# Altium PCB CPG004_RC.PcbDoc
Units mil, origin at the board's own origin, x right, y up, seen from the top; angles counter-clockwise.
Board outline 5000 x 5000 mil, 4 copper layers (Top Layer, Kelvin, GND_Plane, Bottom Layer); 96 components, 88 nets, 618 pads, 128 vias.
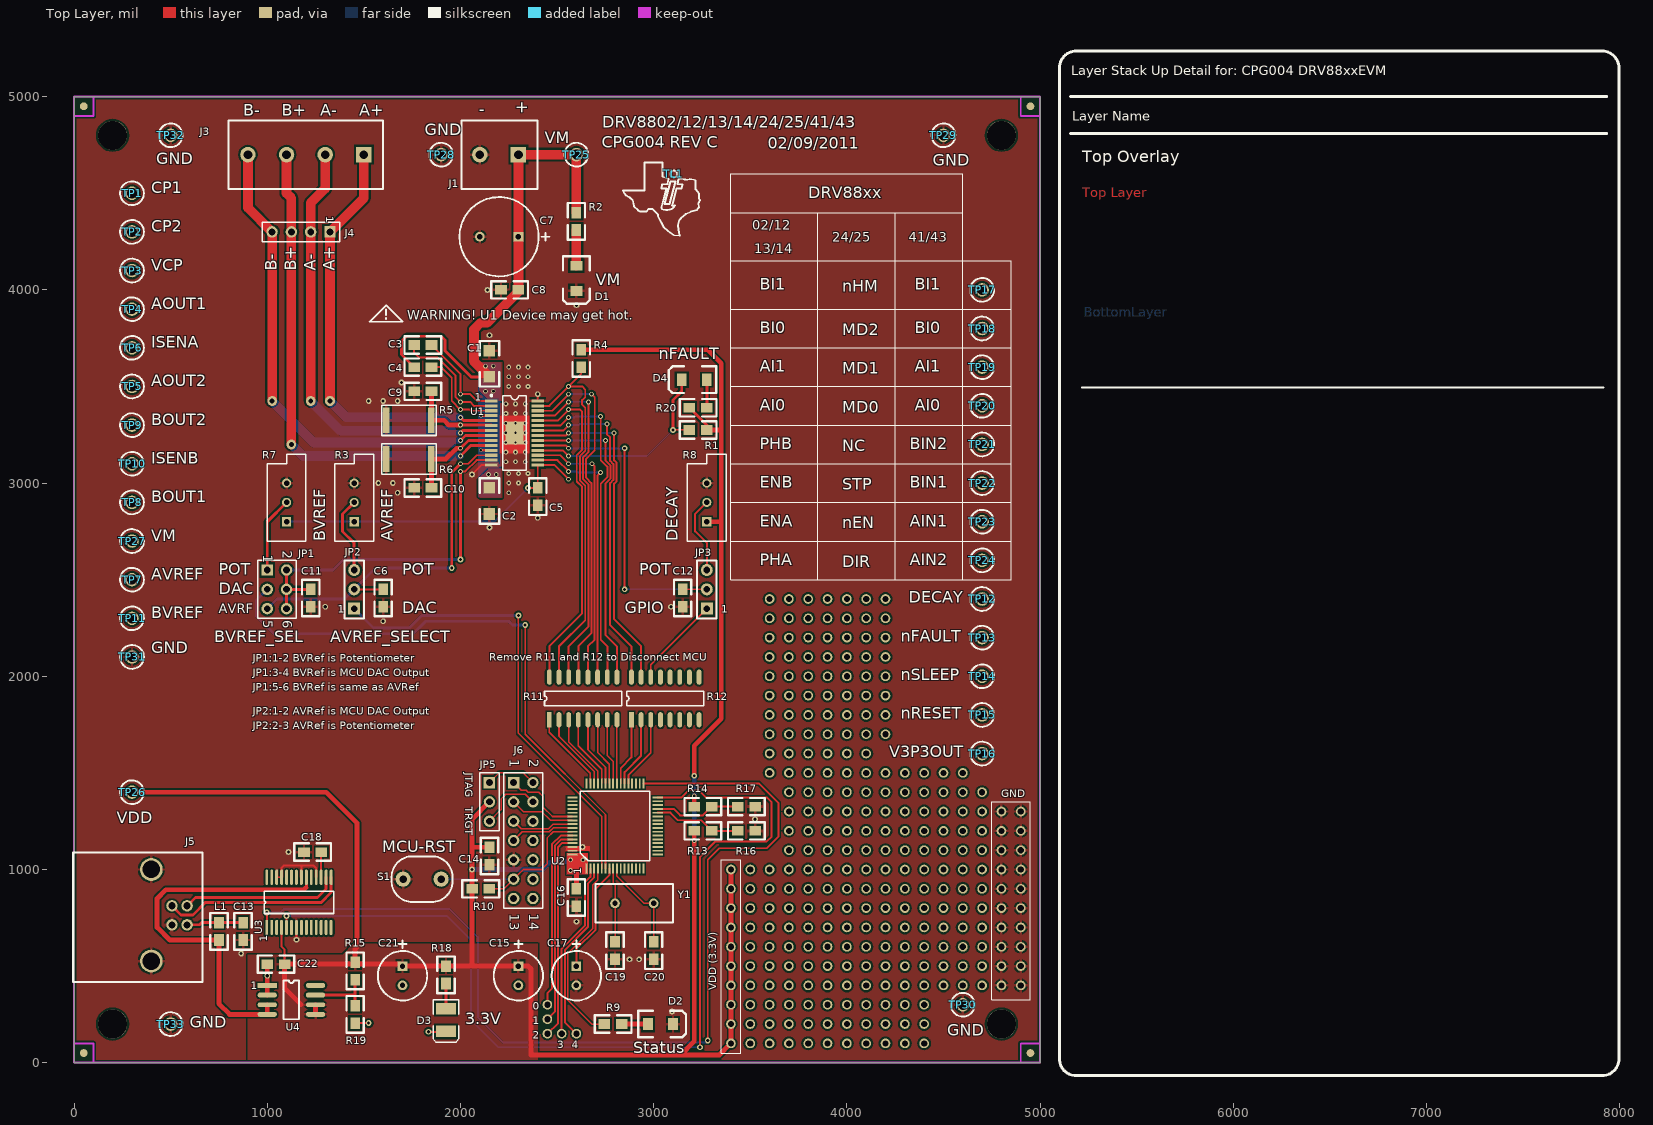
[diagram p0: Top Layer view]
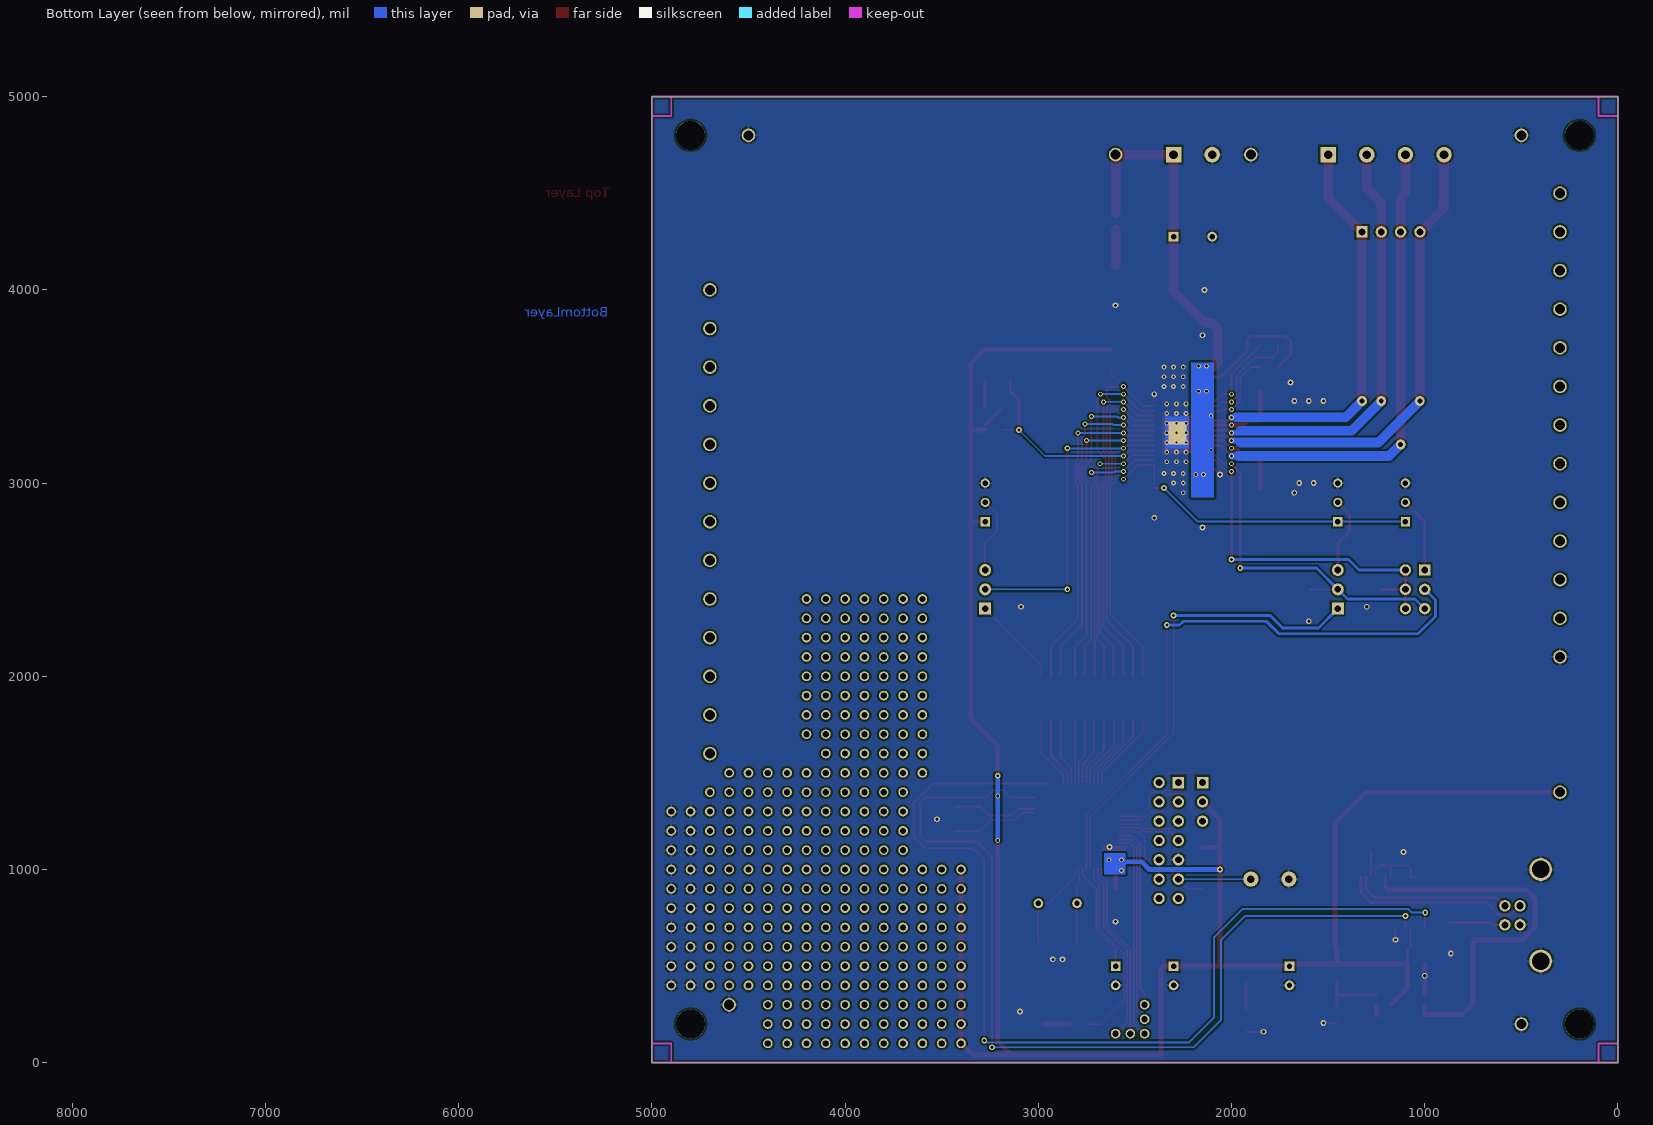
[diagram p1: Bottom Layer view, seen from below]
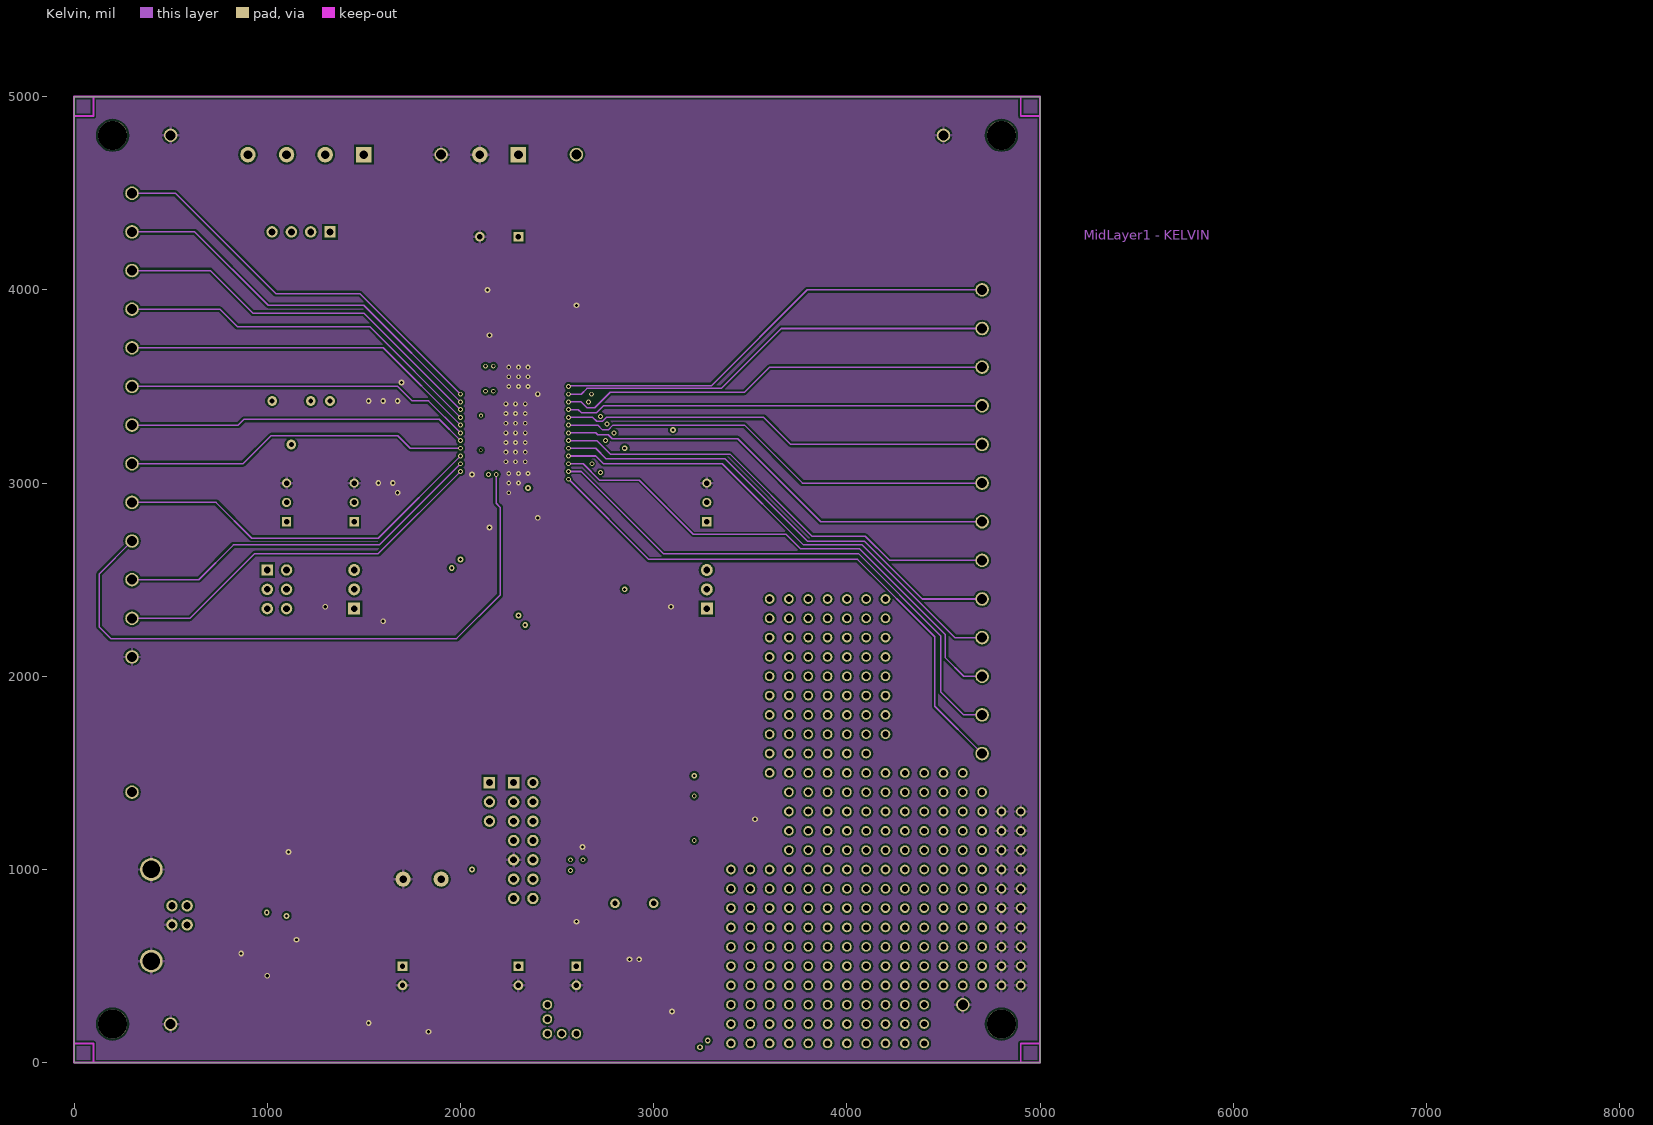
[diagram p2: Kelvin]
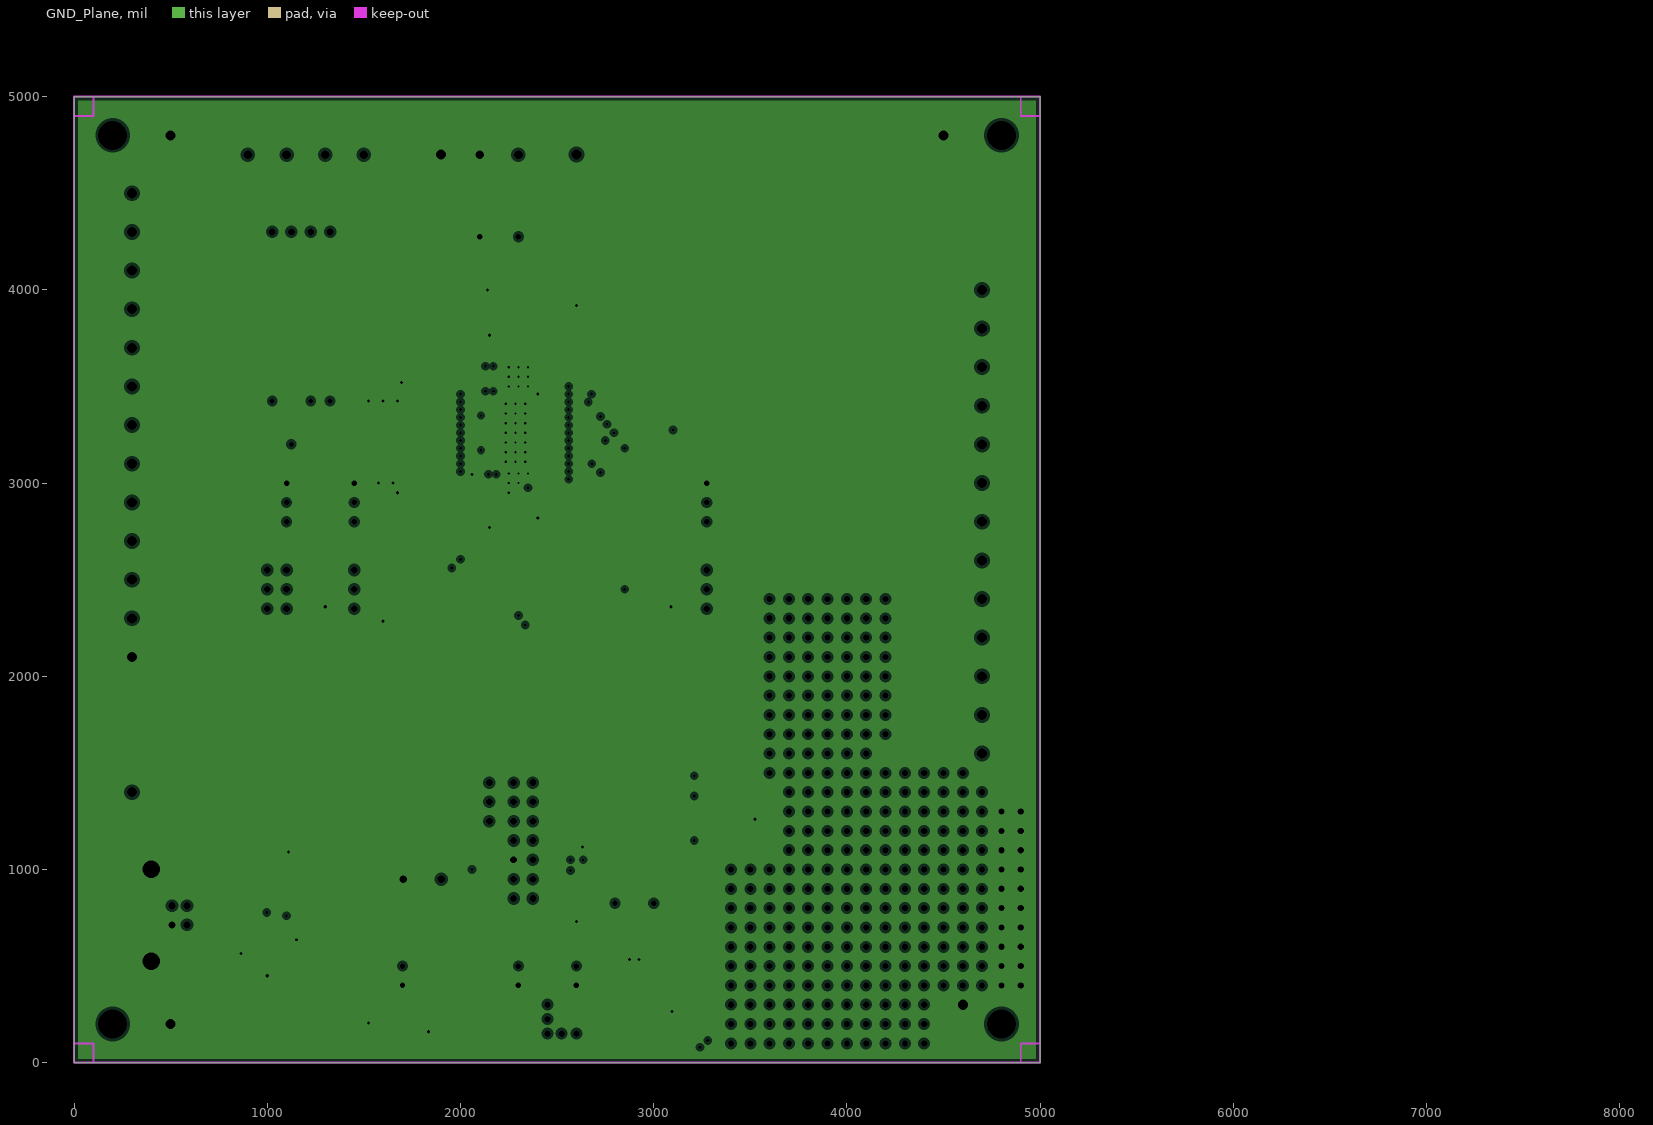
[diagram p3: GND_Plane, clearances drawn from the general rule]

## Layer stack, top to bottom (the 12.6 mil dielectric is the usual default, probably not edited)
Top Layer: signal copper 1.4
Dielectric: core 12.6, FR-4, Dk 4.8
Kelvin: signal copper 1.4
Dielectric: prepreg 12.6, FR-4, Dk 4.8
GND_Plane: plane copper 1.4, net GND
Dielectric: core 12.6, FR-4, Dk 4.8
Bottom Layer: signal copper 1.4

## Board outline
0,0 5000,0 5000,5000 0,5000

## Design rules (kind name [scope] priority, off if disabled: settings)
Clearance Clearance_2 [InNamedPolygon('KLV_GND') Or  InNamedPolygon('TOP_VDD') Or  InNamedPolygon('BOT_GND') Or  InNamedPolygon('TOP_GND')] p1: gap=10
Clearance [All] p2: gap=6
HoleSize [All] p1: absolutevalues=TRUE maxlimit=360 minlimit=1 maxpercent=80.000 minpercent=20.000
PlaneClearance [All] p1: clearance=15
PlaneConnect [All] p1: planeconnectstyle=Relief reliefexpansion=15 reliefentries=4 reliefconductorwidth=20 reliefairgap=8
PolygonConnect GND_VIA [(InNet('GND')) vs IsVia] p1: connectstyle=Direct reliefconductorwidth=10 reliefentries=4 polygonreliefangle="90 Angle"
PolygonConnect PolygonConnect_1 [All vs IsNamedPolygon('TOP_PIN_GND')] p2: connectstyle=Direct reliefconductorwidth=10 reliefentries=4 polygonreliefangle="90 Angle"
PolygonConnect PolygonConnect_2 [All vs IsNamedPolygon('TOP_VM') or isnamedpolygon('TOP_VMB')] p3: connectstyle=Direct reliefconductorwidth=10 reliefentries=4 polygonreliefangle="90 Angle"
PolygonConnect [All] p4: connectstyle=Relief reliefconductorwidth=15 reliefentries=4 polygonreliefangle="90 Angle"
RoutingLayers [All] p1: top layer_v5=TRUE mid layer 1_v5=FALSE bottom layer_v5=TRUE
RoutingVias [All] p1: holewidth=15 width=25 viastyle="Through Hole" minholewidth=10 minwidth=20 maxholewidth=25 maxwidth=70
SilkscreenOverComponentPads [All] p1: minsilkscreentomaskgap=10
SolderMaskExpansion [All] p1: expansion=4
TestPointUsage [All] p1: valid=2 allowmultiple=FALSE
Testpoint [All] p1: side=15 testpointundercomponent=TRUE minsize=40 maxsize=100 preferedsize=60 minholesize=0 maxholesize=40 preferedholesize=32 testpointgrid=1 style=1023 order=0123456789
Width [All] p1: maxlimit=100 minlimit=8 preferedwidth=8 toplayer_prefwidth=10 midlayer1_maxwidth=8 bottomlayer_prefwidth=50 minimp=50.000000 maximp=50.000000 favimp=50.000000
19 further rules are at their usual default settings.

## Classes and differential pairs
component class CPG004_RC_TS: TP1 TP2 TP3 TP4 TP5 TP6 TP7 TP8 TP9 TP10 TP11 TP12 TP13 TP14 TP15 TP16 TP17 TP18 TP19 TP20 TP21 TP22 TP23 TP24 TP25 TP26 TP27 TP28 TP29 TP30 TP31 TP32 TP33
component class CPG004_RC: C1 C2 C3 C4 C5 C6 C7 C8 C9 C10 C11 C12 D1 D4 J1 J3 J4 JP1 JP2 JP3 R1 R2 R3 R4 R5 R6 R7 R8 R20 TL1 U1
polygon class PinPolygons: Bottom-GND VDD
component class CPG004_RC_MSP430: C13 C14 C15 C16 C17 C18 C19 C20 C21 C22 D2 D3 J5 J6 JP5 L1 R9 R10 R11 R12 R13 R14 R15 R16 R17 R18 R19 S1 U2 U3 U4 Y1

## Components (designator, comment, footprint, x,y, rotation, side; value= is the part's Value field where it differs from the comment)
C1 "" 1206 2150,3685 r270 top
C2 "" 1206 2150,2840 r90 top
C3 "0.01uF" 0805 1850,3715 r180 top
C4 "" 0805 1760,3600 r0 top
C5 "" 0805 2400,2885 r90 top
C6 "" 0805 1600,2360 r90 top
C7 "" "RB .2/.4 SS" 2100,4275 r0 top
C8 "" 0805 2210,4000 r0 top
C9 "" 0805 1760,3475 r0 top
C10 "" 0805 1760,2975 r0 top
C11 "" 0805 1225,2360 r90 top
C12 "" 0805 3150,2360 r90 top
C13 "Cap" 0805 875,635 r90 top
C14 "Cap" 0805 2150,1025 r90 top
C15 "Cap Pol1" "RB .1/.250" 2300,400 r270 top
C16 "Cap" 0805 2600,810 r90 top
C17 "Cap Pol1" "RB .1/.250" 2600,400 r270 top
C18 "Cap" 0805 1190,1090 r0 top
C19 "Cap" 0805 2800,535 r90 top
C20 "Cap" 0805 3000,535 r90 top
C21 "Cap Pol1" "RB .1/.250" 1700,400 r270 top
C22 "Cap1" 0805 1000,510 r0 top
D1 "VM" 1206_LED 2600,4125 r270 top
D2 "Status" 1206_LED 2970.08,200 r0 top
D3 "3.3V" 3.5X2.8X1.9 1925,220.94 r270 top
D4 "nFAULT" 1206_LED 3275,3535 r180 top
J1 "VM" PWR_CONN2 2300,4700 r180 top
J3 "Header 4" PWR_CONN4 1500,4700 r180 top
J4 "Header 4" HDR1X4 1325,4300 r180 top
J5 "USB B Conn" USB_CONN 506.69,812.2 r270 top
J6 "JTAG" HDR2X7 2275,1450 r270 top
JP1 "BVREF_SEL" HDR2X3 1000,2550 r270 top
JP2 "AVREF_SELECT" JMP0.3 1450,2350 r90 top
JP3 "DECAY_SEL" JMP0.3 3275,2350 r90 top
JP5 "PWR Select" HDR1X3 2150,1450 r270 top
L1 "" 0805 750,725 r270 top
R1 "" 0805 3275,3275 r180 top
R2 "Res2" 0805 2600,4400 r270 top
R3 "AVREF" VR5 1450,2900 r90 top
R4 "" 0805 2625,3690 r270 top
R5 "" 2512 1850,3325 r180 top
R6 "" 2512 1850,3125 r180 top
R7 "BVREF" VR5 1100,2900 r90 top
R8 "DECAY" VR5 3275,2900 r90 top
R9 "Res2" 0805 2835.08,200 r180 top
R10 "" 0805 2060,900 r0 top
R11 "Res Pack3" RES_NET_8 2460,1775 r90 top
R12 "Res Pack3" RES_NET_8 2885,1775 r90 top
R13 "" 0805 3210,1200 r0 top
R14 "" 0805 3210,1325 r0 top
R15 "Res2" 0805 1455,430 r90 top
R16 "" 0805 3435,1200 r0 top
R17 "" 0805 3435,1325 r0 top
R18 "Res1" 0805 1925,410 r90 top
R19 "Res2" 0805 1455,205 r90 top
R20 "Res2" 0805 3275,3390 r180 top
S1 "MCU-RST" Pana_PB 1703.15,950 r0 top
TL1 "DRV8802/12/13/14/24/25/41/43" "TI LOGO" 3105,4600 r0 top
TP1 "CP1" "TEST POINT 0.052" 300,4500 r90 top
TP2 "CP2" "TEST POINT 0.052" 300,4300 r90 top
TP3 "VCP" "TEST POINT 0.052" 300,4100 r0 top
TP4 "AOUT1" "TEST POINT 0.052" 300,3900 r0 top
TP5 "AOUT2" "TEST POINT 0.052" 300,3500 r0 top
TP6 "ISENA" "TEST POINT 0.052" 300,3700 r0 top
TP7 "AVREF" "TEST POINT 0.052" 300,2500 r0 top
TP8 "BOUT1" "TEST POINT 0.052" 300,2900 r0 top
TP9 "BOUT2" "TEST POINT 0.052" 300,3300 r0 top
TP10 "ISENB" "TEST POINT 0.052" 300,3100 r270 top
TP11 "BVREF" "TEST POINT 0.052" 300,2300 r0 top
TP12 "DECAY" "TEST POINT 0.052" 4700,2400 r0 top
TP13 "nFAULT" "TEST POINT 0.052" 4700,2200 r90 top
TP14 "nSLEEP" "TEST POINT 0.052" 4700,2000 r0 top
TP15 "nRESET" "TEST POINT 0.052" 4700,1800 r0 top
TP16 "V3P3OUT" "TEST POINT 0.052" 4700,1600 r0 top
TP17 "BI1/nHM/BI1" "TEST POINT 0.052" 4700,4000 r90 top
TP18 "BI0/MD2/BI0" "TEST POINT 0.052" 4700,3800 r90 top
TP19 "AI1/MD1/AI1" "TEST POINT 0.052" 4700,3600 r90 top
TP20 "AI0/MD0/AI0" "TEST POINT 0.052" 4700,3400 r90 top
TP21 "PHB/NC/BIN2" "TEST POINT 0.052" 4700,3200 r0 top
TP22 "ENB/STP/BIN1" "TEST POINT 0.052" 4700,3000 r90 top
TP23 "ENA/nEN/AIN1" "TEST POINT 0.052" 4700,2800 r90 top
TP24 "PHA/DIR/AIN2" "TEST POINT 0.052" 4700,2600 r90 top
TP25 "VM" "TEST POINT 0.052" 2600,4700 r90 top
TP26 "VDD" "TEST POINT 0.052" 300,1400 r90 top
TP27 "VM" "TEST POINT 0.052" 300,2700 r90 top
TP28 "GND" "TEST POINT 0.052" 1900,4700 r90 top
TP29 "GND" "TEST POINT 0.052" 4500,4800 r90 top
TP30 "GND" "TEST POINT 0.052" 4600,300 r90 top
TP31 "GND" "TEST POINT 0.052" 300,2100 r0 top
TP32 "GND" "TEST POINT 0.052" 500,4800 r0 top
TP33 "GND" "TEST POINT 0.052" 500,200 r90 top
U1 "DRV88xx" "HTSSOP28 - PWP" 2159.84,3425.59 r270 top
U2 "MSP430F1612" MSP430F1612 2800,1225 r90 top
U3 "FTD232R" FT232RL 997.64,700 r90 top
U4 "TPS77701" TL7726 1000,400 r0 top
Y1 "8 MHZ" XTAL 3000,825 r180 top

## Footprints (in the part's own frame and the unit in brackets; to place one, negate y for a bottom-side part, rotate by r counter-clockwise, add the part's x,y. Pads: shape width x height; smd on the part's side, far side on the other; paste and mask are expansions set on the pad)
3.5X2.8X1.9 [mm] "SM LED; 2 C-Bend Leads; Body 3.5 x 2.8 x 1.9 mm, inc leads (LxWxH typ)"
  rect 1.5x2.6 smd: 1(-1.5,0) 2(1.5,0)
  silkscreen extent -2.65,-1.7 2.95,1.7
0805 [mil]
  rect 60x50 smd: 1(0,0) 2(90,0)
  silkscreen extent -50,-45 140,45
1206 [mil]
  rect 60x60 smd: 1(0,0) 2(135,0)
  silkscreen extent -50,-50 185,50
1206_LED [mm]
  rect 1.3x1.6 smd: 1(0,0) 2(3.3,0)
  silkscreen extent -1.25,-1.75 5,1.75
2512 [mm]
  rect 0.85x3.4 smd: 1(0,0) 2(5.93,0)
  silkscreen extent -0.64,-2 6.57,2
FT232RL [mm]
  rect 2x0.381 smd: 1(0,0)
  oval 2x0.381 smd: 2(0,-0.65) 3(0,-1.3) 4(0,-1.95) 5(0,-2.6) 6(0,-3.25) 7(0,-3.9) 8(0,-4.55) 9(0,-5.2) 10(0,-5.85) 11(0,-6.5) 12(0,-7.15) 13(0,-7.8) 14(0,-8.45) 15(6.6,-8.45) 16(6.6,-7.8) 17(6.6,-7.15) 18(6.6,-6.5) 19(6.6,-5.85) 20(6.6,-5.2) 21(6.6,-4.55) 22(6.6,-3.9) 23(6.6,-3.25) 24(6.6,-2.6) 25(6.6,-1.95) 26(6.6,-1.3) 27(6.6,-0.65) 28(6.6,0)
  silkscreen extent 1.84,-8.78 4.76,0.33
HDR1X3 [mm] "Connector; Header; 3 Position"
  rect 1.5x1.5 hole 0.889: 1(0,0)
  round 1.5 hole 0.889: 2(2.54,0) 3(5.08,0)
  silkscreen extent -1.27,-1.27 6.35,1.27
HDR1X4 [mm] "Connector; Header; 4 Position"
  rect 1.5x1.5 hole 0.889: 1(0,0)
  round 1.5 hole 0.889: 2(2.54,0) 3(5.08,0) 4(7.62,0)
  silkscreen extent -1.27,-1.27 8.89,1.27
HDR2X3 [mm] "Connector; Header; 3x2 Position"
  rect 1.5x1.5 hole 0.889: 1(0,0)
  round 1.5 hole 0.889: 2(0,2.54) 3(2.54,0) 4(2.54,2.54) 5(5.08,0) 6(5.08,2.54)
  silkscreen extent -1.27,-1.27 6.35,3.81
HDR2X7 [mm] "Connector; Header; 7x2 Position"
  rect 1.5x1.5 hole 0.889: 1(0,0)
  round 1.5 hole 0.889: 2(0,2.54) 3(2.54,0) 4(2.54,2.54) 5(5.08,0) 6(5.08,2.54) 7(7.62,0) 8(7.62,2.54) 9(10.16,0) 10(10.16,2.54) 11(12.7,0) 12(12.7,2.54) 13(15.24,0) 14(15.24,2.54)
  silkscreen extent -1.27,-1.27 16.51,3.81
"HTSSOP28 - PWP" [mm] "Shrink Small Outline; 28 Leads; Body Width 4.4 mm; Pitch 0.65 mm"
  rect 3.04x2.34 smd: 0(4.225,3.05)
  rect 3.04x2.34 smd far side: 0(4.225,3.05)
  rect 0.4x1.65 smd: 1(0,0) 2(0.65,0) 3(1.3,0) 4(1.95,0) 5(2.6,0) 6(3.25,0) 7(3.9,0) 8(4.55,0) 9(5.2,0) 10(5.85,0) 11(6.5,0) 12(7.15,0) 13(7.8,0) 14(8.45,0) 15(8.45,6.1) 16(7.8,6.1) 17(7.15,6.1) 18(6.5,6.1) 19(5.85,6.1) 20(5.2,6.1) 21(4.55,6.1) 22(3.9,6.1) 23(3.25,6.1) 24(2.6,6.1) 25(1.95,6.1) 26(1.3,6.1) 27(0.65,6.1) 28(0,6.1)
  silkscreen extent -0.82,-0.12 9.13,4.6
JMP0.3 [mil]
  rect 62x62 hole 35: 1(0,0)
  round 62 hole 35: 2(100,0) 3(200,0)
  silkscreen extent -50,-50 250,50
MSP430F1612 [mm]
  rect 1.35x0.25 smd: 1(-5.6,3.75) 2(-5.6,3.25) 3(-5.6,2.75) 4(-5.6,2.25) 5(-5.6,1.75) 6(-5.6,1.25) 7(-5.6,0.75) 8(-5.6,0.25) 9(-5.6,-0.25) 10(-5.6,-0.75) 11(-5.6,-1.25) 12(-5.6,-1.75) 13(-5.6,-2.25) 14(-5.6,-2.75) 15(-5.6,-3.25) 16(-5.6,-3.75) 33(5.6,-3.75) 34(5.6,-3.25) 35(5.6,-2.75) 36(5.6,-2.25) 37(5.6,-1.75) 38(5.6,-1.25) 39(5.6,-0.75) 40(5.6,-0.25) 41(5.6,0.25) 42(5.6,0.75) 43(5.6,1.25) 44(5.6,1.75) 45(5.6,2.25) 46(5.6,2.75) 47(5.6,3.25) 48(5.6,3.75)
  rect 0.25x1.35 smd: 17(-3.75,-5.6) 18(-3.25,-5.6) 19(-2.75,-5.6) 20(-2.25,-5.6) 21(-1.75,-5.6) 22(-1.25,-5.6) 23(-0.75,-5.6) 24(-0.25,-5.6) 25(0.25,-5.6) 26(0.75,-5.6) 27(1.25,-5.6) 28(1.75,-5.6) 29(2.25,-5.6) 30(2.75,-5.6) 31(3.25,-5.6) 32(3.75,-5.6) 49(3.75,5.6) 50(3.25,5.6) 51(2.75,5.6) 52(2.25,5.6) 53(1.75,5.6) 54(1.25,5.6) 55(0.75,5.6) 56(0.25,5.6) 57(-0.25,5.6) 58(-0.75,5.6) 59(-1.25,5.6) 60(-1.75,5.6) 61(-2.25,5.6) 62(-2.75,5.6) 63(-3.25,5.6) 64(-3.75,5.6)
  silkscreen extent -4.56,-4.56 4.56,4.56
Pana_PB [mm] "Panasonic EVQ-11A04M Push Button"
  round 2 hole 1: 1(0,0) 2(5,0)
  silkscreen extent -1.51,-3 6.51,3
PWR_CONN2 [mil]
  rect 80x80 hole 45: 1(0,0)
  round 80 hole 45: 2(200,0)
  silkscreen extent -98,-177 295,177
PWR_CONN4 [mil]
  rect 80x80 hole 45: 1(0,0)
  round 80 hole 45: 2(200,0) 3(400,0) 4(600,0)
  silkscreen extent -98,-177 700,177
"RB .1/.250" [mil]
  rect 50x50 hole 28: 1(-100,0)
  round 50 hole 28: 2(0,0)
  silkscreen extent -234,-128 78,128
"RB .2/.4 SS" [mil] "Reduced Size Footprint (Plus is closer to Body for better Clearance)"
  rect 50x50 hole 28: 1(200,0)
  round 50 hole 28: 2(0,0)
  silkscreen extent -105,-205 360,205
RES_NET_8 [mm]
  rect 2x0.63 smd: 1(0,0)
  oval 2x0.63 smd: 2(0,-1.27) 3(0,-2.54) 4(0,-3.81) 5(0,-5.08) 6(0,-6.35) 7(0,-7.62) 8(0,-8.89) 9(5.6,-8.89) 10(5.6,-7.62) 11(5.6,-6.35) 12(5.6,-5.08) 13(5.6,-3.81) 14(5.6,-2.54) 15(5.6,-1.27) 16(5.6,0)
  silkscreen extent 1.84,-9.53 3.76,0.64
"TEST POINT 0.052" [mil] "Glass Beaded Test Point"
  round 70 hole 52: 1(0,0)
  silkscreen extent -61,-62 61,61
"TI LOGO" [mil] "TI BUG"
  silkscreen extent -264,-320 135,59
TL7726 [mil]
  rect 100x25 smd: 1(0,0)
  oval 100x25 smd: 2(0,-50) 3(0,-100) 4(0,-150) 5(250,-150) 6(250,-100) 7(250,-50) 8(250,0)
  silkscreen extent 85,-175 165,25
USB_CONN [mm] "USB Right Angle receptacle"
  round 1.5 hole 0.93: 1(2.5,2) 2(0,2) 3(0,0) 4(2.5,0)
  round 3 hole 2.3: 5(-4.77,-2.71) 6(7.27,-2.71)
  silkscreen extent -7,-13 10,4
VR5 [mm] "Potentiometer; 3 Leads"
  rect 1.2x1.2 hole 0.711: 1(-2.54,0)
  round 1.2 hole 0.711: 2(0,0) 3(2.54,0)
  silkscreen extent -5.08,-2.54 6.35,2.54
XTAL [mil]
  round 50 hole 28: 1(0,0) 2(200,0)
  silkscreen extent -100,-100 300,100

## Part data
C1 C2: library part Cap, "CAP .10UF 50V CERAMIC X7R 1206"
C3: library part Cap, "CAP 10000PF 50V CERAMIC X7R 0805"
C4 C6 C8 C9 C10 C11 C12: library part Cap, "CAP .10UF 50V CERAMIC X7R 0805"
C5: library part Cap, "CAP CER .47UF 25V X7R 0805 FO"
C7: library part "Cap Pol1", "CAP 100UF 50V ELECT M RADIAL"
C13 C14 C16 C18 C22: "CAP .10UF 50V CERAMIC X7R 0805"
C15 C17 C21: "CAP 10UF 25V ELECT VR RADIAL"
C19 C20: "CAP CERAMIC 33PF 50V NP0 0805"
D1 D2 D3 D4: library part LED3, "LED RED CLEAR 1206 SMD"
J1: library part "Header 2", "TERM BLOCK 5.08MM VERT 2POS PCB"
J3: "TERM BLOCK 5.08MM VERT 4POS PCB"
J4: "CONN HEADER .100 SINGL STR 3POS"
J5: library part USB_B_CONN, "CONN USB RT ANG RECPT TYPE B BLK"
J6: library part "Header 7X2H", "CONN HEADER .100 DUAL STR 14POS"
JP1: library part "Header 3X2", "CONN HEADER .100 DUAL STR 6POS"
JP2 JP3: library part "JUMPER 3 PIN", "CONN HEADER .100 SINGL STR 3POS"
JP5: library part "Header 3", "CONN HEADER .100 SINGL STR 3POS"
L1: library part Inductor, "FERRITE 1.5A 40 OHM 0805 SMD"
R1 R4 R10 R13 R14: library part Res1, "RES 3.3K OHM 1/8W 5% 0805 SMD"
R2: "RES 3.3K OHM 1/8W 5% 0805 SMD"
R3 R7: library part RPot, "TRIMPOT CERM 10K OHM 12TRN TOP"
R5 R6: library part Res1, "RES .4OHM 1W 1% 2010 SMD"
R8: library part RPot, "TRIMPOT CERM 5K OHM 12TRN TOP"
R9 R18 R20: "RES 330 OHM 1/8W 5% 0805 SMD"
R11 R12: "RES NET 8RES 220 OHM 16PIN SMD"
R15: "RES 196K OHM 1/8W 1% 0805 SMD"
R16 R17: library part Res1, "RES 0.0 OHM 1/8W 5% 0805 SMD"
R19: "RES 110K OHM 1/8W 5% 0805 SMD"
S1: library part SW-PB, "SWITCH LIGHT TOUCH 4.3MM 100GF"
TL1: library part TI_LOGO, "CPG004 Bare Board"
TP1 TP2 TP3 TP4 TP5 TP6 TP7 TP8 TP9 TP10 TP11 TP12 TP13 TP14 TP15 TP16 TP17 TP18 TP19 TP20 TP21 TP22 TP23 TP24: library part "TEST POINT", "Test Points LG WHT TERM"
TP25 TP26 TP27: library part "TEST POINT", "Test Points LG RED TERM"
TP28 TP29 TP30 TP31 TP32 TP33: library part "TEST POINT", "Test Points LG BLACK TERM"
U1: library part Io_Europa, "Stepper / DC Motor Driver"
U2: "IC MCU 16BIT 55K FLASH 64-LQFP"
U3: library part FT232R, "IC USB TO SERIAL UART 28-SSOP"
U4: "IC ADJ 750MA LDO REG 8-SOIC"
Y1: library part XTAL, "CRYSTAL 8.00 MHZ 20PF 49US"

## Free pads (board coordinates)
  round 40 smd: 0(50,50) 0(50,4950) 0(4950,50) 0(4950,4950)
  round 150 hole 150: 0(200,200) 0(200,4800) 0(4800,200) 0(4800,4800)
  round 50 hole 32: 0(3600,1900) 0(3600,2000) 0(3600,2100) 0(3600,2200) 0(3600,2300) 0(3600,2400) 0(3700,1200) 0(3700,1800) 0(3700,1900) 0(3700,2000) 0(3700,2100) 0(3700,2200) 0(3700,2300) 0(3700,2400) 0(3800,1200) 0(3800,1800) 0(3800,1900) 0(3800,2000) 0(3800,2100) 0(3800,2200) 0(3800,2300) 0(3800,2400) 0(3900,1200) 0(3900,1800) 0(3900,1900) 0(3900,2000) 0(3900,2100) 0(3900,2200) 0(3900,2300) 0(3900,2400) 0(4000,1200) 0(4000,1800) 0(4000,1900) 0(4000,2000) 0(4000,2100) 0(4000,2200) 0(4000,2300) 0(4000,2400) 0(4100,1200) 0(4100,1800) 0(4100,1900) 0(4100,2000) 0(4100,2100) 0(4100,2200) 0(4100,2300) 0(4100,2400) 0(4200,1200) 0(4200,1800) 0(4200,1900) 0(4200,2000) 0(4200,2100) 0(4200,2200) 0(4200,2300) 0(4200,2400) 0(4300,1200) 0(4400,1200) 0(4500,1200) 0(4600,1200) 0(4700,1200) 0(4800,1200) 0(4900,1200) 1(3600,1800) 1(3700,1100) 1(3700,1700) 1(3800,1100) 1(3800,1700) 1(3900,1100) 1(3900,1700) 1(4000,1100) 1(4000,1700) 1(4100,1100) 1(4100,1700) 1(4200,1100) 1(4200,1700) 1(4300,1100) 1(4400,1100) 1(4500,1100) 1(4600,1100) 1(4700,1100) 1(4800,1100) 1(4900,1100) 2(3400,1000) 2(3500,1000) 2(3600,1000) 2(3600,1700) 2(3700,1000) 2(3700,1600) 2(3800,1000) 2(3800,1600) 2(3900,1000) 2(3900,1600) 2(4000,1000) 2(4000,1600) 2(4100,1000) 2(4100,1600) 2(4200,1000) 2(4300,1000) 2(4400,1000) 2(4500,1000) 2(4600,1000) 2(4700,1000) 2(4800,1000) 2(4900,1000) 3(3400,900) 3(3500,900) 3(3600,900) 3(3600,1600) 3(3700,900) 3(3700,1500) 3(3800,900) 3(3800,1500) 3(3900,900) 3(3900,1500) 3(4000,900) 3(4000,1500) 3(4100,900) 3(4100,1500) 3(4200,900) 3(4200,1500) 3(4300,900) 3(4400,900) 3(4500,900) 3(4600,900) 3(4700,900) 3(4800,900) 3(4900,900) 4(3400,800) 4(3500,800) 4(3600,800) 4(3700,800) 4(3700,1400) 4(3800,800) 4(3800,1400) 4(3900,800) 4(3900,1400) 4(4000,800) 4(4000,1400) 4(4100,800) 4(4100,1400) 4(4200,800) 4(4200,1400) 4(4300,800) 4(4400,800) 4(4500,800) 4(4600,800) 4(4700,800) 4(4800,800) 4(4900,800) 5(3400,200) 5(3400,500) 5(3400,700) 5(3500,200) 5(3500,500) 5(3500,700) 5(3600,200) 5(3600,500) 5(3600,700) 5(3700,200) 5(3700,500) 5(3700,700) 5(3700,1300) 5(3800,200) 5(3800,500) 5(3800,700) 5(3800,1300) 5(3900,200) 5(3900,500) 5(3900,700) 5(3900,1300) 5(4000,200) 5(4000,500) 5(4000,700) 5(4000,1300) 5(4100,200) 5(4100,500) 5(4100,700) 5(4100,1300) 5(4200,200) 5(4200,500) 5(4200,700) 5(4200,1300) 5(4300,200) 5(4300,500) 5(4300,700) 5(4400,200) 5(4400,500) 5(4400,700) 5(4500,500) 5(4500,700) 5(4600,500) 5(4600,700) 5(4700,500) 5(4700,700) 5(4800,500) 5(4800,700) 5(4900,500) 5(4900,700) 6(3400,100) 6(3400,300) 6(3400,400) 6(3400,600) 6(3500,100) 6(3500,300) 6(3500,400) 6(3500,600) 6(3600,100) 6(3600,300) 6(3600,400) 6(3600,600) 6(3700,100) 6(3700,300) 6(3700,400) 6(3700,600) 6(3800,100) 6(3800,300) 6(3800,400) 6(3800,600) 6(3900,100) 6(3900,300) 6(3900,400) 6(3900,600) 6(4000,100) 6(4000,300) 6(4000,400) 6(4000,600) 6(4100,100) 6(4100,300) 6(4100,400) 6(4100,600) 6(4200,100) 6(4200,300) 6(4200,400) 6(4200,600) 6(4300,100) 6(4300,300) 6(4300,400) 6(4300,600) 6(4400,100) 6(4400,300) 6(4400,400) 6(4400,600) 6(4500,400) 6(4500,600) 6(4600,400) 6(4600,600) 6(4700,400) 6(4700,600) 6(4800,400) 6(4800,600) 6(4900,400) 6(4900,600) 12(2450,300) 13(2450,225) 14(2524,150) 15(2450,150) 16(2600,150) 17(4300,1300) 18(4300,1400) 19(4300,1500) 20(4400,1500) 21(4400,1300) 22(4500,1300) 23(4600,1300) 24(4400,1400) 25(4800,1300) 25(4900,1300) 26(4700,1300) 29(3600,1500) 30(4500,1500) 31(4500,1400) 32(4600,1500) 33(4600,1400) 34(4700,1400)

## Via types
v1: diameter 25, hole 15, Top Layer to Bottom Layer, 43 vias
v2: diameter 25, hole 12, Top Layer to Bottom Layer, 36 vias
v3: diameter 30, hole 16, Top Layer to Bottom Layer, 27 vias
v4: diameter 30, hole 15, Top Layer to Bottom Layer, 16 vias
v5: diameter 50, hole 25, Top Layer to Bottom Layer, 4 vias
v6: diameter 20, hole 12, Top Layer to Bottom Layer, 2 vias

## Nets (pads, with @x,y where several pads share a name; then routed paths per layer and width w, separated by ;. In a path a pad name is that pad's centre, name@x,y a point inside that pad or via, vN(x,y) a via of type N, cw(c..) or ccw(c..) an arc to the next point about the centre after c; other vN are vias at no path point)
5VCC: L1.2 U3.20 U4.3 U4.4 | length 2012.9
  Top Layer w15: 1190,895 1202.36,907.36 U3.20
  Top Layer w25: U4.3 U4.4 805,250 750,305 L1.2 495,635 430,700 430,850 475,895 1190,895 1200.28,905.28
AGVREF: JP2.1 U2.5 | length 2407.4
  Top Layer w8: v4(2300,2315) 2300,1705 2731.1,1273.9 U2.5
  Bottom Layer w15: JP2.1 1550,2250 1735,2250 1800,2315 v4(2300,2315)
AI0/MD0/AI0: R11.16 TP20.1 U1.24 | length 3886.5
  Top Layer w10: U1.24 2503.23,3323.23 v1(2560,3380) 2620,3380 2630,3370 2630,3172.88 2602,3144.88 2602,3008.12 2630,2980.12 2630,2325 2460,2155 R11.16
  Kelvin w8: v1(2560,3380) 2610,3380 2625,3365 2705,3365 2740,3400 TP20.1
AI1/MD1/AI1: R11.14 TP19.1 U1.25 | length 4020.9
  Top Layer w10: U1.25 2488.82,3348.82 v1(2560,3420) ; R11.14 2560,2155 2662,2257 2662,2993.37 2634,3021.37 2634,3131.63 2662,3159.63 v1(2662,3420)
  Kelvin w8: v1(2560,3420) 2625,3420 2655,3390 2695,3390 2775,3470 3470,3470 3600,3600 TP19.1
  Bottom Layer w8: v1(2560,3420) v1(2662,3420)
ANA0: pad.12 U2.59 | length 964.8
  Top Layer w10: pad.12 2450,360 2473,383 2473,1129.67 2519.12,1175.79 U2.59
ANA1: pad.13 U2.60 | length 1018.4
  Top Layer w10: pad.13 2489,264 2489,1123.04 2522.06,1156.1 U2.60
ANA2: pad.15 U2.61 | length 1072
  Top Layer w10: pad.15 2505,205 2505,1116.42 2525,1136.42 U2.61
ANA3: pad.14 U2.2 | length 915.9
  Top Layer w10: pad.14 2524,589 2644,709 2644,934 2672.05,962.05 U2.2
ANA4: pad.16 U2.3 | length 942.2
  Top Layer w10: pad.16 2540,210 2540,582.37 2660,702.37 2660,927.37 2691.73,959.11 U2.3
AOUT1: J3.1 J4.1 TP4.1 U1.5 | length 4186.4
  Top Layer w15: v1(2000,3340) 2016.77,3323.23 U1.5
  Top Layer w50: v5(1325,3425) J4.1 1500,4475 J3.1
  Kelvin w8: TP4.1 755,3900 845,3810 1530,3810 v1(2000,3340)
  Bottom Layer w35: 1945,3340 v1(2000,3340)
  Bottom Layer w50: v5(1325,3425) 1410,3340 1945,3340 1975,3340
AOUT2: J3.2 J4.2 TP5.1 U1.7 | length 4114.5
  Top Layer w15: v1(2000,3260) 2012.05,3272.05 U1.7
  Top Layer w50: v5(1225,3425) J4.2 1225,4450 1300,4525 J3.2
  Kelvin w8: TP5.1 1675,3500 1750,3425 1835,3425 v1(2000,3260)
  Bottom Layer w30: 1950,3260 v1(2000,3260)
  Bottom Layer w50: v5(1225,3425) 1380,3270 1955,3270
AVREF: C6.2 JP1.5 JP2.2 TP7.1 U1.12 | length 3877.3
  Top Layer w10: JP2.2 C6.2 ; v1(2000,3100) 2040,3100 2084.09,3144.09 U1.12
  Top Layer w15: v4(1955,2560) 1955,3055 v1(2000,3100)
  Kelvin w8: TP7.1 645,2500 825,2680 1580,2680 v1(2000,3100)
  Bottom Layer w15: JP1.5 1050,2400 1400,2400 JP2.2 1560,2560 v4(1955,2560)
BGVREF: JP1.3 U2.6 | length 3058
  Top Layer w8: v4(2335,2265) 2335,1700 2750.79,1284.21 U2.6
  Bottom Layer w15: JP1.3 945,2395 945,2310 1035,2220 1755,2220 1820,2285 2250,2285 2270,2265 v4(2335,2265)
BI0/MD2/BI0: R11.13 TP18.1 U1.26 | length 4124.3
  Top Layer w10: U1.26 2474.41,3374.41 v1(2560,3460) ; R11.13 2610,2155 2678,2223 2678,3000 2650,3028 2650,3125 2695,3170 2695,3443 v1(2678,3460)
  Kelvin w8: v1(2560,3460) 2625,3460 2655,3490 3350,3490 3660,3800 TP18.1
  Bottom Layer w10: v1(2560,3460) v1(2678,3460)
BI1/NHM/BI1: R4.2 R11.15 TP17.1 U1.27 | length 4349.4
  Top Layer w10: U1.27 2460,3400 v1(2560,3500) ; R11.15 2510,2155 2646,2291 2646,2986.75 2618,3014.75 2618,3138.25 2646,3166.25 2646,3390 2630,3406 2630,3429 2646,3445 2646,3484 2630,3500 v1(2560,3500) ; R4.2 2625,3565 v1(2560,3500)
  Kelvin w8: v1(2560,3500) 2564,3504 3299,3504 3795,4000 TP17.1
BOUT1: J3.3 J4.3 TP8.1 U1.10 | length 4545.6
  Top Layer w15: v1(2000,3140) 2055.28,3195.28 U1.10
  Top Layer w50: J3.3 1100,4500 1125,4475 J4.3 v5(1125,3200)
  Kelvin w8: TP8.1 735,2900 920,2715 1575,2715 v1(2000,3140)
  Bottom Layer w35: 1965,3140 v1(2000,3140)
  Bottom Layer w50: v5(1125,3200) 1185,3140 1965,3140
BOUT2: J3.4 J4.4 TP9.1 U1.8 | length 4324.6
  Top Layer w15: v1(2000,3220) 2026.46,3246.46 U1.8
  Top Layer w50: J3.4 900,4425 J4.4 v5(1025,3425)
  Kelvin w8: TP9.1 850,3300 880,3330 1890,3330 v1(2000,3220)
  Bottom Layer w30: 1950,3220 v1(2000,3220)
  Bottom Layer w50: v5(1025,3425) 1240,3210 1955,3210
BVREF: C11.2 JP1.2 JP1.4 JP1.6 TP11.1 U1.13 | length 3901.7
  Top Layer w10: v1(2000,3060) 2025,3060 2083.5,3118.5 U1.13
  Top Layer w15: JP1.6 JP1.4 ; JP1.2 JP1.4 ; C11.2 JP1.4 ; v4(2000,2605) v1(2000,3060)
  Kelvin w8: TP11.1 600,2300 935,2635 1575,2635 v1(2000,3060)
  Bottom Layer w15: JP1.2 1340,2550 1395,2605 v4(2000,2605)
CBUS0: U3.23
CBUS1: U3.22
CBUS2: U3.13
CBUS3: U3.14
CBUS4: U3.12
CP1: C3.1 TP1.1 U1.1 | length 2622
  Top Layer w10: C3.1 2000,3565 v1(2000,3460) 2050,3460 2084.41,3425.59 U1.1
  Kelvin w8: TP1.1 525,4500 1045,3980 1480,3980 v1(2000,3460)
CP2: C3.2 TP2.1 U1.2 | length 2682.7
  Top Layer w10: C3.2 1760,3675 1785,3650 1880,3650 1975,3555 1975,3445 v1(2000,3420) 2050,3420 2070,3400 U1.2
  Kelvin w8: TP2.1 625,4300 1005,3920 1500,3920 v1(2000,3420)
CTS: U3.11
DCD: U3.10
DECAY: C12.2 JP3.2 TP12.1 U1.19 | length 4199.4
  Top Layer w8: C12.2 JP3.2
  Top Layer w10: U1.19 2544.72,3195.28 v1(2560,3180) ; v4(2850,2450) v4(2850,3180)
  Kelvin w8: v1(2560,3180) 2700,3180 2755,3125 3370,3125 3795,2700 4090,2700 4390,2400 TP12.1
  Bottom Layer w8: v4(2850,2450) JP3.2
  Bottom Layer w10: v1(2560,3180) v4(2850,3180)
DSR: U3.9
DTR: U3.2
ENA/NEN/AIN1: R12.15 TP23.1 U1.21 | length 4064.4
  Top Layer w10: U1.21 2546.46,3246.46 v1(2560,3260) ; v1(2795,3260) 2795,3117.88 2808,3104.88 2808,3010.12 2795,2997.12 2795,2295 2935,2155 R12.15
  Kelvin w8: v1(2560,3260) 2700,3260 2710,3250 2765,3250 2785,3230 3435,3230 3865,2800 TP23.1
  Bottom Layer w10: v1(2560,3260) v1(2795,3260)
ENB/STP/BIN1: R12.16 TP22.1 U1.22 | length 4032.8
  Top Layer w10: U1.22 2532.05,3272.05 v1(2560,3300) ; v1(2758,3305) 2758,3253.5 2775,3236.5 2775,3115.25 2792,3098.25 2792,3016.75 2775,2999.75 2775,2265 2885,2155 R12.16
  Kelvin w8: v1(2560,3300) 2710,3300 2735,3275 2765,3275 2790,3300 3470,3300 3770,3000 TP22.1
  Bottom Layer w10: v1(2560,3300) 2610,3300 2615,3305 v1(2758,3305)
GDECAY: JP3.1 R12.14 | length 474.6
  Top Layer w8: 2985,2060 JP3.1
  Top Layer w10: R12.14 2985,2060
GND: C1.1 C2.1 C5.1 C6.1 C7.2 C8.1 C9.1 C10.1 C11.1 C12.1 C13.1 C14.1 C15.2 C16.1 C17.2 C18.1 C19.1 C20.1 C21.2 C22.1 D1.2 D2.2 D3.2 J1.2 J5.4 J5.5 J5.6 J6.9 pad.0@4800,1200 pad.0@4900,1200 pad.1@4800,1100 pad.1@4900,1100 pad.2@4800,1000 pad.2@4900,1000 pad.3@4800,900 pad.3@4900,900 pad.4@4800,800 pad.4@4900,800 pad.5@4800,500 pad.5@4800,700 pad.5@4900,500 pad.5@4900,700 pad.6@4800,400 pad.6@4800,600 pad.6@4900,400 pad.6@4900,600 pad.25 R3.3 R5.2 R6.2 R7.3 R8.3 R16.2 R17.2 R19.1 S1.1 TP28.1 TP29.1 TP30.1 TP31.1 TP32.1 TP33.1 U1.0 U1.14 U1.28 U2.62 U2.63 U3.7 U3.18 U3.21 U3.25 U3.26 U4.1 U4.2 | length 992
  Top Layer w10: U3.26 U3.25 1074.41,1009.41 1085,1020 1175,1020 ; v3(1110,1090) v3@1115,1085 ; v4(1151.18,636.18) U3.7 ; U3.21 1176.77,1018.23 ; U3.18 1253.54,1006.46 1240,1020 1178.54,1020 ; R19.1 v3(1525,205) ; v3(1835,160) 1923.11,160 D3.2 ; v4(2060,3045) 2107.91,3092.91 U1.14 ; U1.28 v4(2400,3460) ; U2.63 U2.62 v4(2631.73,1116.73) ; 1175,1020 1178.54,1020 ; 1175,1020 1176.77,1018.23 ; 1176.77,1018.23 1178.54,1020
  Top Layer w25: U4.2 U4.1 v3(1000,450) C22.1
  other v2: 2250,2950 2250,3000 2300,3000 2250,3050 2300,3050 2350,3050 2235,3110 2285,3110 2335,3110 2235,3160 2285,3160 2335,3160 2235,3210 2285,3210 2335,3210 2235,3260 2285,3260 2335,3260 2235,3310 2285,3310 2335,3310 2235,3360 2285,3360 2335,3360 2235,3410 2285,3410 2335,3410 2250,3500 2300,3500 2350,3500 2250,3550 2300,3550 2350,3550 2250,3600 2300,3600 2350,3600
  other v3: 3095,265 2875,535 2925,535 865,565 2600,730 3525,1260 1600,2285 1300,2360 3090,2360 2150,2770 2400,2820 1675,2950 1575,3000 1650,3000 1525,3425 1600,3425 1675,3425 1695,3520 2150,3765 2600,3920 2140,4000
ISENA: C9.2 R5.1 TP6.1 U1.6 | length 2336.9
  Top Layer w15: v1(2000,3300) 2157.48,3300 U1.6
  Top Layer w25: C9.2 R5.1 1915,3325 1940,3300 v1(2000,3300)
  Kelvin w8: TP6.1 1600,3700 v1(2000,3300)
ISENB: C10.2 R6.1 TP10.1 U1.9 | length 2286.5
  Top Layer w15: v1(2000,3180) 2040.87,3220.87 U1.9
  Top Layer w25: C10.2 R6.1 1925,3125 1980,3180 v1(2000,3180)
  Kelvin w8: TP10.1 875,3100 1020,3245 1675,3245 1740,3180 v1(2000,3180)
NetC13_2: C13.2 J5.1 L1.1 | length 294.2
  Top Layer w15: J5.1 648.78,713.78 660,725 L1.1 C13.2
NetC17_1: C17.1 U2.7 | length 575.1
  Top Layer w10: C17.1 2600,588.79 2700,688.79 2700,900 2770.47,970.47 U2.7
NetC18_2: C18.2 U3.17 | length 130.5
  Top Layer w10: U3.17 1279.13,1089.13 C18.2
NetC19_2: C19.2 U2.8 Y1.2 | length 383.6
  Top Layer w8: U2.8 2790.16,929.84 2800,920 Y1.2 C19.2
NetC20_2: C20.2 U2.9 Y1.1 | length 487.6
  Top Layer w8: U2.9 2809.84,965.16 2950,825 Y1.1 C20.2
NetD1_1: D1.1 R2.2 | length 185
  Top Layer w50: D1.1 R2.2
NetD2_1: D2.1 R9.1 | length 135
  Top Layer w25: R9.1 D2.1
NetD3_1: D3.1 R18.1 | length 130
  Top Layer w15: D3.1 R18.1
NetD4_1: D4.1 R20.1 | length 145
  Top Layer w15: R20.1 D4.1
NetJ6_1: J6.1 U2.54 | length 409.6
  Top Layer w8: J6.1 2315,1410 2340,1410 2350,1400 2405,1400 2425,1380 2425,1325 2475.79,1274.21 U2.54
NetJ6_2: J6.2 JP5.1 | length 266.4
  Top Layer w8: JP5.1 2200,1500 2325,1500 J6.2
NetJ6_3: J6.3 U2.55 | length 344.1
  Top Layer w8: J6.3 2325,1300 2420,1300 2465.47,1254.53 U2.55
NetJ6_4: J6.4 JP5.3 | length 331.8
  Top Layer w8: JP5.3 2210,1310 2210,1365 2235,1390 2335,1390 J6.4
NetJ6_5: J6.5 U2.56 | length 331
  Top Layer w8: J6.5 2314.53,1210.47 2455.47,1210.47 2479.84,1234.84 U2.56
NetJ6_7: J6.7 U2.57 | length 331.5
  Top Layer w8: J6.7 2320,1195 2460,1195 2480.16,1215.16 U2.57
NetJP1_1: JP1.1 R7.2 | length 391.4
  Top Layer w15: JP1.1 1000,2800 R7.2
NetJP2_3: JP2.3 R3.2 | length 399.7
  Top Layer w15: JP2.3 1450,2690 1390,2750 1390,2840 R3.2
NetJP3_3: JP3.3 R8.2 | length 399.7
  Top Layer w10: JP3.3 3275,2690 3215,2750 3215,2840 R8.2
NetR11_1: R11.1 U2.47 | length 417.4
  Top Layer w8: R11.1 2460,1710 2672.05,1497.95 U2.47
NetR11_2: R11.2 U2.46 | length 404.8
  Top Layer w8: R11.2 2510,1690 2691.73,1508.27 U2.46
NetR11_3: R11.3 U2.45 | length 392.2
  Top Layer w8: R11.3 2560,1660 2711.42,1508.58 U2.45
NetR11_4: R11.4 U2.44 | length 379.7
  Top Layer w8: R11.4 2610,1640 2731.1,1518.9 U2.44
NetR11_5: R11.5 U2.43 | length 367.1
  Top Layer w8: R11.5 2660,1620 2750.79,1529.21 U2.43
NetR11_6: R11.6 U2.42 | length 354.6
  Top Layer w8: R11.6 2710,1605 2770.47,1544.53 U2.42
NetR11_7: R11.7 U2.41 | length 342
  Top Layer w8: R11.7 2760,1590 2790.16,1559.84 U2.41
NetR11_8: R11.8 U2.40 | length 329.6
  Top Layer w8: U2.40 2809.84,1774.84 R11.8
NetR12_1: R12.1 U2.39 | length 352.5
  Top Layer w10: U2.39 2829.53,1524.53 2885,1580 R12.1
NetR12_2: R12.2 U2.38 | length 365.1
  Top Layer w10: U2.38 2849.21,1504.21 2935,1590 R12.2
NetR12_3: R12.3 U2.37 | length 377.6
  Top Layer w10: U2.37 2868.9,1488.9 2985,1605 R12.3
NetR15_1: R15.1 R19.2 U4.7 | length 340
  Top Layer w15: U4.7 1455,350 ; R19.2 1455,350 ; R15.1 1455,350
NFAULT: D4.2 R1.2 TP13.1 U1.18 | length 3661.2
  Top Layer w8: v4(3100,3275) R1.2
  Top Layer w10: U1.18 2530.31,3169.69 v1(2560,3140)
  Top Layer w15: v4(3100,3275) 3100,3430 3145.08,3475.08 D4.2
  Kelvin w8: v1(2560,3140) 2700,3140 2740,3100 3355,3100 3775,2680 4080,2680 4560,2200 TP13.1
  Bottom Layer w8: v1(2560,3140) 2965,3140 v4(3100,3275)
NRESET: R11.11 TP15.1 U1.16 | length 4248.8
  Top Layer w10: U1.16 2501.5,3118.5 v1(2560,3060) ; R11.11 2710,3040 v1(2725,3055)
  Kelvin w8: v1(2560,3060) 2625,3060 3050,2635 4060,2635 4485,2210 4485,1920 4605,1800 TP15.1
  Bottom Layer w10: v1(2560,3060) 2605,3060 2610,3055 v1(2725,3055)
NSLEEP: R11.12 TP14.1 U1.17 | length 4268.6
  Top Layer w10: U1.17 2515.91,3144.09 v1(2560,3100) ; R11.12 2660,2155 2694,2189 2694,3086 v1(2680,3100)
  Kelvin w8: v1(2560,3100) 2635,3100 2720,3015 2925,3015 3205,2735 3400,2735 ; 3580,2735 3400,2735 ; TP14.1 4605,2000 4510,2095 4510,2215 4066,2659 3761,2659 3685,2735 3400,2735
  Bottom Layer w10: v1(2560,3100) v1(2680,3100)
OSCI: U3.27
OSCO: U3.28
P6M5: R9.2 U2.4 | length 986.2
  Top Layer w8: U2.4 2711.42,946.43 2685,920.01 2685,695 2555,565 2555,325 2680,200 R9.2
PHA/DIR/AIN2: R11.9 TP24.1 U1.20 | length 4018.1
  Top Layer w10: U1.20 2400.87,3220 v1(2560,3220) ; v1(2750,3220) 2750,3117.63 2776,3091.63 2776,3023.37 2750,2997.37 2750,2215 2810,2155 R11.9
  Kelvin w8: v1(2560,3220) 2705,3220 2775,3150 3395,3150 3820,2725 4095,2725 4220,2600 TP24.1
  Bottom Layer w10: v1(2560,3220) v1(2750,3220)
PHB/NC/BIN2: R11.10 TP21.1 U1.23 | length 3951.4
  Top Layer w10: U1.23 2517.64,3297.64 v1(2560,3340) ; v1(2725,3345) 2726,3344 2726,3119 2760,3085 2760,3030 2726,2996 2726,2189 2760,2155 R11.10
  Kelvin w8: v1(2560,3340) 2685,3340 2705,3320 2735,3320 2755,3340 3570,3340 3710,3200 TP21.1
  Bottom Layer w10: v1(2560,3340) 2590,3340 2595,3345 v1(2725,3345)
RESET: U3.19
RI: U3.6
RST: J6.11 R10.2 S1.2 U2.58 | length 1006
  Top Layer w8: R10.2 2225,900 J6.11 2325,1000 2420,1000 2450,1030 2450,1165 2480.47,1195.47 U2.58
  Bottom Layer w8: S1.2 J6.11
RTS: U3.3
RX: U2.32 U3.5 | length 4931.7
  Top Layer w10: U3.5 v4(1100,760) ; U2.32 3145,1372.64 3182.36,1410 3232.64,1410 3270,1372.64 3585,1372.64 3610,1347.64 3610,1170 3585,1145 3320,1145 3240,1065 v3(3240,80)
  Bottom Layer w10: v4(1100,760) 1930,760 2055,635 2055,220 2195,80 v3(3240,80)
SEL0: R13.2 R16.1 U2.28 | length 453.4
  Top Layer w10: U2.28 3086.1,1293.9 3125,1255 3245,1255 R13.2 R16.1
SEL1: R14.2 R17.1 U2.29 | length 447.1
  Top Layer w10: U2.29 3103.58,1313.58 3137.16,1280 3255,1280 R14.2 R17.1
TX: U2.33 U3.1 | length 5164.8
  Top Layer w10: U3.1 v4(997.64,777.64) ; U2.33 3544.53,1445.47 3645,1345 3645,1170 3585,1110 3340,1110 3280,1050 v3(3280,115)
  Bottom Layer w10: v4(997.64,777.64) 1067.64,777.64 1085,795 1944.5,795 2090,649.5 2090,234.5 2219.5,105 3228.23,105 3229.23,106 3250.77,106 3251.77,105 3270,105 v3(3280,115)
USBDM: J5.2 U3.16 | length 815.7
  Top Layer w15: J5.2 628.23,855 1260,855 1304.72,899.72 U3.16
USBDP: J5.3 U3.15 | length 970.5
  Top Layer w15: J5.3 553.9,765 615,765 680,830 1280,830 1330.32,880.32 U3.15
V3P3OUT: C5.2 R3.1 R7.1 TP16.1 U1.15 | length 4619.7
  Top Layer w10: v4(2350,2975) C5.2 U1.15 2487.09,3092.91 v1(2560,3020)
  Kelvin w8: v1(2560,3020) 2975,2605 4055,2605 4455,2205 4455,1845 TP16.1
  Bottom Layer w10: R7.1 R3.1 2175,2800 v4(2350,2975)
VCP: C4.2 TP3.1 U1.3 | length 2471.8
  Top Layer w10: C4.2 1900,3600 1955,3545 1955,3425 v1(2000,3380) 2048.82,3380 2054.41,3374.41 U1.3
  Kelvin w8: TP3.1 705,4100 925,3880 1500,3880 v1(2000,3380)
VDD: C14.2 C15.1 C16.2 C21.1 C22.2 JP5.2 pad.2@3400,1000 pad.3@3400,900 pad.4@3400,800 pad.5@3400,200 pad.5@3400,500 pad.5@3400,700 pad.6@3400,100 pad.6@3400,300 pad.6@3400,400 pad.6@3400,600 R1.1 R4.1 R8.1 R10.1 R13.1 R14.1 R15.2 R18.2 R20.2 TP26.1 U2.1 U2.64 U3.4 U4.5 U4.6 | length 12591.5
  Top Layer w10: U3.4 1074.41,600.59 1090,585 C22.2
  Top Layer w15: R20.2 3275,3300
  Top Layer w25: TP26.1 1305,1400 1465,1240 1465,600 1455,590 R15.2 ; 1175,300 1090,385 C22.2 1455,510 1690,510 C21.1 R18.2 2060,500 ; U4.5 U4.6 ; C14.2 2065,1115 2060,1120 ; JP5.2@2150,1345 JP5.2 2060,1260 2060,1120 ; C16.2 2600,1000 ; R4.1 3280,3690 3350,3620 3350,3275 ; R13.1 v1(3210,1150) 3210,110 3140,40 ; R14.1 v1(3210,1380) ; v4(3210,1485) 3210,1640 3350,1780 3350,2800 ; R8.1 3350,2800 ; R1.1 3350,3275 ; pad.2@3400,1000 3400,900 3400,800 3400,700 3400,600 3400,500 3400,400 3400,300 3400,200 3400,100 3340,40 3140,40 ; 2060,500 C15.1 2350,500 2365,485 2365,40 3140,40 ; 2060,500 R10.1 v4(2060,1000) 2060,1120 ; 3350,2800 3350,3275
  Bottom Layer w25: v4(2060,1000) 2425,1000 2465,1040 2570,1040 2610,1040 ; v1(3210,1150) v1(3210,1380) v4(3210,1485)
  other v1: 2570,995 2570,1050 2635,1050
VM: C1.2 C2.2 C4.1 C7.1 C8.2 J1.1 R2.1 TP25.1 TP27.1 U1.4 U1.11 | length 6094.7
  Top Layer w15: C4.1 1695,3665 1695,3735 1720,3760 1900,3760 1920,3740 1920,3685 2055,3550 C1.2 ; v6(2105.31,3169.69) U1.11 ; v6(2106.18,3348.82) U1.4
  Top Layer w50: C1.2 2112.5,3587.5 2070,3630 2070,3795 2105,3830 2138.84,3830 2300,3991.16 C8.2 C7.1 J1.1 TP25.1 R2.1
  Kelvin w8: TP27.1 130,2530 130,2255 190,2195 1980,2195 2205,2420 2205,2875 2185,2895 v1(2185,3045)
  other v1: 2145,3045 2130,3475 2170,3475 2130,3605 2170,3605
pads on no net: J6.6 J6.8 J6.10 J6.12 J6.13 J6.14 R12.4 R12.5 R12.6 R12.7 R12.8 R12.9 R12.10 R12.11 R12.12 R12.13 U2.10 U2.11 U2.12 U2.13 U2.14 U2.15 U2.16 U2.17 U2.18 U2.19 U2.20 U2.21 U2.22 U2.23 U2.24 U2.25 U2.26 U2.27 U2.30 U2.31 U2.34 U2.35 U2.36 U2.48 U2.49 U2.50 U2.51 U2.52 U2.53 U3.8 U3.24 U4.8
copper on no net: | length 42.7
  Kelvin w8: 3895,1600 3900,1600 ; 4080,2400 4100,2400 ; 4212.5,2212.5 4225,2200

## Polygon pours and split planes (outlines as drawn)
VM on Top Layer "TOP_VMB" (solid, pour order 1001): 2100,2925 2215,2925 2215,3075 2145,3075 2140,3070 2095,3025 2095,2930 2100,2925
VM on Top Layer "TOP_VM" (solid, pour order 1000): 2215,3425 2215,3625 2100,3625 2100,3475 2150,3425
GND on Top Layer "TOP_GND" (solid, pour order 1006): 0,0 5000,0 5000,5000 0,5000 0,0
VDD on Top Layer "TOP_VDD" (solid, pour order 1003): 2400,0 2400,615 1445,615 1390,560 900,560 900,0
GND on Top Layer "TOP_PIN_GND" (solid, pour order 1002): 2198.32,3079.04 2139.62,3079.04 2070.58,3010 2020,3010 2020,3055 2070,3105 2197.95,3105 2198.32,3104.63
GND on Kelvin "KLV_GND" (solid, pour order 1004): 0,0 5000,0 5000,5000 0,5000 0,0
GND on Bottom Layer "BOT_GND" (solid, pour order 1005): 0,0 5000,0 5000,5000 0,5000 0,0
GND on GND_Plane (split plane): 4979.9,20.1 20.1,20.1 20.1,4979.9 4979.9,4979.9

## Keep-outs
Keep-Out Layer:
  lines w10: 0,100 100,100 100,0 ; 0,4900 100,4900 100,5000 ; 4900,0 4900,100 5000,100 ; 4900,5000 4900,4900 5000,4900 ; 0,0 5000,0 5000,5000 0,5000 0,0

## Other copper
Top Layer:
  rectangle net GND: 2202.32,3151.81 2357.52,3350
  rectangle net VDD: 2550,975 2660,1085
  rectangle net GND: 2542.95,1095 2670,1121.12
  text "Top Layer" at 5217,4480 h50
Kelvin:
  text "MidLayer1 - KELVIN" at 5227,4260 h50
Bottom Layer:
  rectangle net GND: 2220.2,3180 2345,3345
  rectangle net VDD: 2550,975 2660,1085
  rectangle net VM: 2090,2925 2210,3625
  text "BottomLayer" at 5227,3860 h50
GND_Plane (plane layer: these items are gaps in the copper):
  text "PLANE - GND" at 5227,4060 h50

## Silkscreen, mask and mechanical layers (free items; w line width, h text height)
Top Overlay:
  lines w3.94: 3400,2700 4850,2700 ; 3400,2900 4850,2900 ; 3400,3100 4850,3100 ; 3400,3300 4850,3300 ; 3400,3500 4850,3500 ; 3400,3700 4850,3700 ; 3400,3900 4850,3900 ; 3400,4150 4850,4150 4850,2500 3400,2500 3400,4400 ; 3850,2500 3850,4400 ; 4250,2500 4250,4400 ; 4600,2500 4600,4600 3400,4600 3400,4400 ; 4600,4400 3400,4400 ; 3350,50 3450,50 3450,1050 3350,1050 3350,50 ; 4750,325 4750,1350 4950,1350 4950,325 4750,325
  lines w10: 1615.22,3849.78 1615.22,3854.78 ; 1615.22,3869.78 1615.22,3899.78 ; 5217,3495 7917,3495 ; 1530.22,3834.78 1615.22,3919.78 1700.22,3834.78 1530.22,3834.78
  lines w15: 5100,19 5100,5149 cw(c5187,5149) 5187,5236 7909,5236 cw(c7909,5149) 7996,5149 7996,19 ; 5100,20 ccw(c5187,20) 5187,-67 7909,-67 ccw(c7909,20) 7996,20 ; 5157,4810 7933,4810 ; 5157,5000 7933,5000
  text "Layer Stack Up Detail for: CPG004 DRV88xxEVM" at 5162,5110 h50
  text "-" at 2125,4950 h60 r180
  text "+" at 2345,4910 h60 r90
  text "B-" at 875,4900 h60
  text "B+" at 1075,4900 h60
  text "A-" at 1275,4900 h60
  text "A+" at 1475,4900 h60
  text "Layer Name" at 5167,4875 h50
  text "CPG004 REV C" at 2730,4735 h60
  text "02/09/2011" at 3590,4730 h60
  text "Top Overlay" at 5217,4660 h60
  text "DRV88xx" at 3800,4475 h60
  text "1" at 1305,4380 h40 r270
  text "02/12" at 3510,4310 h50
  text "24/25" at 3925,4250 h50
  text "41/43" at 4320,4250 h50
  text "13/14" at 3520,4190 h50
  text "B-" at 1050,4100 h60 r90
  text "B+" at 1150,4100 h60 r90
  text "A-" at 1250,4100 h60 r90
  text "A+" at 1350,4100 h60 r90
  text "BI1" at 3550,4000 h60
  text "BI1" at 4350,4000 h60
  text "nHM" at 3975,3990 h60
  text "WARNING! U1 Device may get hot." at 1725,3845 h50
  text "BI0" at 3550,3775 h60
  text "BI0" at 4350,3775 h60
  text "MD2" at 3975,3765 h60
  text "AI1" at 3550,3575 h60
  text "AI1" at 4350,3575 h60
  text "MD1" at 3975,3565 h60
  text "1" at 2075,3425 h40
  text "AI0" at 3550,3375 h60
  text "AI0" at 4350,3375 h60
  text "MD0" at 3975,3365 h60
  text "PHB" at 3550,3175 h60
  text "BIN2" at 4325,3175 h60
  text "NC" at 3975,3165 h60
  text "ENB" at 3550,2975 h60
  text "BIN1" at 4325,2975 h60
  text "STP" at 3975,2965 h60
  text "ENA" at 3550,2775 h60
  text "AIN1" at 4325,2775 h60
  text "nEN" at 3975,2765 h60
  text "PHA" at 3550,2575 h60
  text "AIN2" at 4325,2575 h60
  text "DIR" at 3975,2565 h60
  text "POT" at 750,2525 h60
  text "POT" at 1700,2525 h60
  text "POT" at 2925,2525 h60
  text "DAC" at 750,2425 h60
  text "1" at 1365,2330 h40
  text "1" at 3350,2330 h40
  text "AVRF" at 750,2325 h50
  text "DAC" at 1700,2325 h60
  text "GPIO" at 2850,2325 h60
  text "Remove R11 and R12 to Disconnect MCU" at 2150,2080 h40
  text "JP1:1-2 BVRef is Potentiometer" at 925,2075 h40
  text "JP1:3-4 BVRef is MCU DAC Output" at 925,2000 h40
  text "JP1:5-6 BVRef is same as AVRef" at 925,1925 h40
  text "JP2:1-2 AVRef is MCU DAC Output" at 925,1800 h40
  text "JP2:2-3 AVRef is Potentiometer" at 925,1725 h40
  text "JTAG" at 2025,1500 h40 r270
  text "GND" at 4800,1375 h40
  text "TRGT" at 2025,1325 h40 r270
  text "1" at 2625,975 h40 r90
  text "1" at 1000,625 h40 r90
  text "1" at 915,380 h40
  text "VDD (3.3V)" at 3325,375 h40 r90
  text "0" at 2375,275 h40
  text "1" at 2375,200 h40
  text "2" at 2375,125 h40
  text "3" at 2500,75 h40
  text "4" at 2575,75 h40
Mechanical 1:
  the board outline again, w3.94
Drill Drawing:
  text ".LEGEND" at 8157,4680 h40
  text "Drill Drawing." at 8157,4580 h40
  text "Notes:" at 5217,3305 h60
  text "1.  NUMBER OF FINISHED LAYERS:  4" at 5217,3105 h60
  text "2.  BOARD MATERIAL AND CONSTRUCTION TO BE UL" at 5217,2905 h60
  text "APPROVED AND MARKED ON THE FINISHED BOARD." at 5417,2705 h60
  text "3.  LAMINATE MATERIAL: COPPER-CLAD FR-4" at 5217,2505 h60
  text "4.  COPPER WEIGHT: 2oz FINISHED" at 5217,2305 h60
  text "5.  FINISHED THICKNESS: .063 +/- .010" at 5217,2105 h60
  text "6.  MIN PLATING THICKNESS IN THROUGH HOLES: .001\"" at 5217,1905 h60
  text "7.  Surface Finish: Lead Free HASL" at 5217,1705 h60
  text "8.  LPI SOLDERMASK BOTH SIDES USING APPROPRIATE" at 5217,1505 h60
  text "LAYER ARTWORK:  COLOR = BLUE" at 5417,1305 h60
  text "9.  LPI SILKSCREEN AS REQUIRED:  COLOR - WHITE" at 5217,1105 h60
  text "10.  VENDOR INFORMATION TO BE INCORPORATED" at 5217,905 h60
  text "ON BACK SIDE WHENEVER POSSIBLE" at 5417,705 h60
  text "11.  MINIMUM COPPER CONDUCTOR WIDTH IS: 8 MILS" at 5217,505 h60
  text "12. MINIMUM CONDUCTOR SPACING IS: 6 MILS" at 5217,305 h60

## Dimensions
0,5200 to 5000,5200 on Mechanical 1
-200,0 to -300,5000 on Mechanical 1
